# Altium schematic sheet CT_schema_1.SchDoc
size 623 x 258 mm
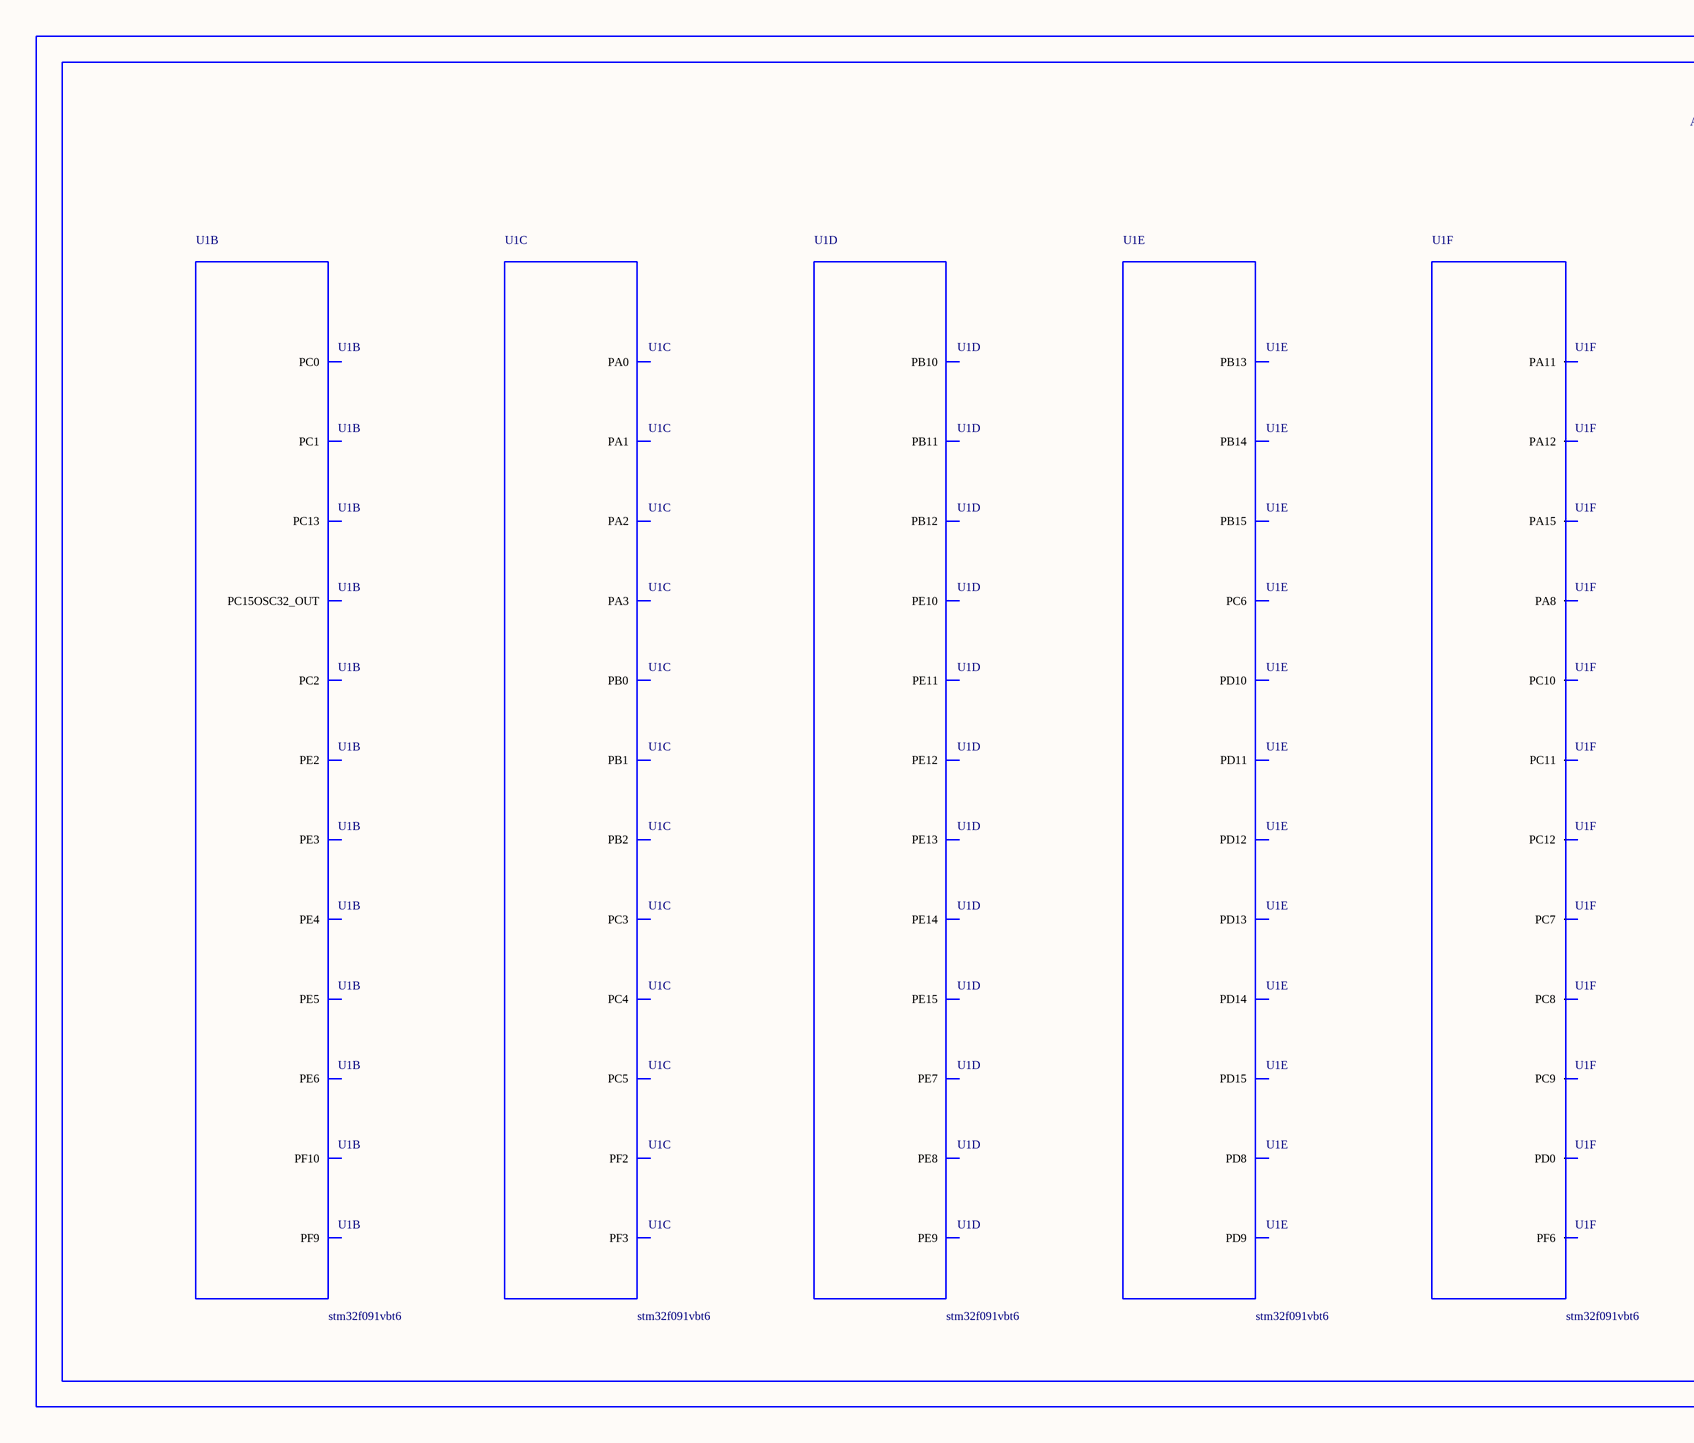
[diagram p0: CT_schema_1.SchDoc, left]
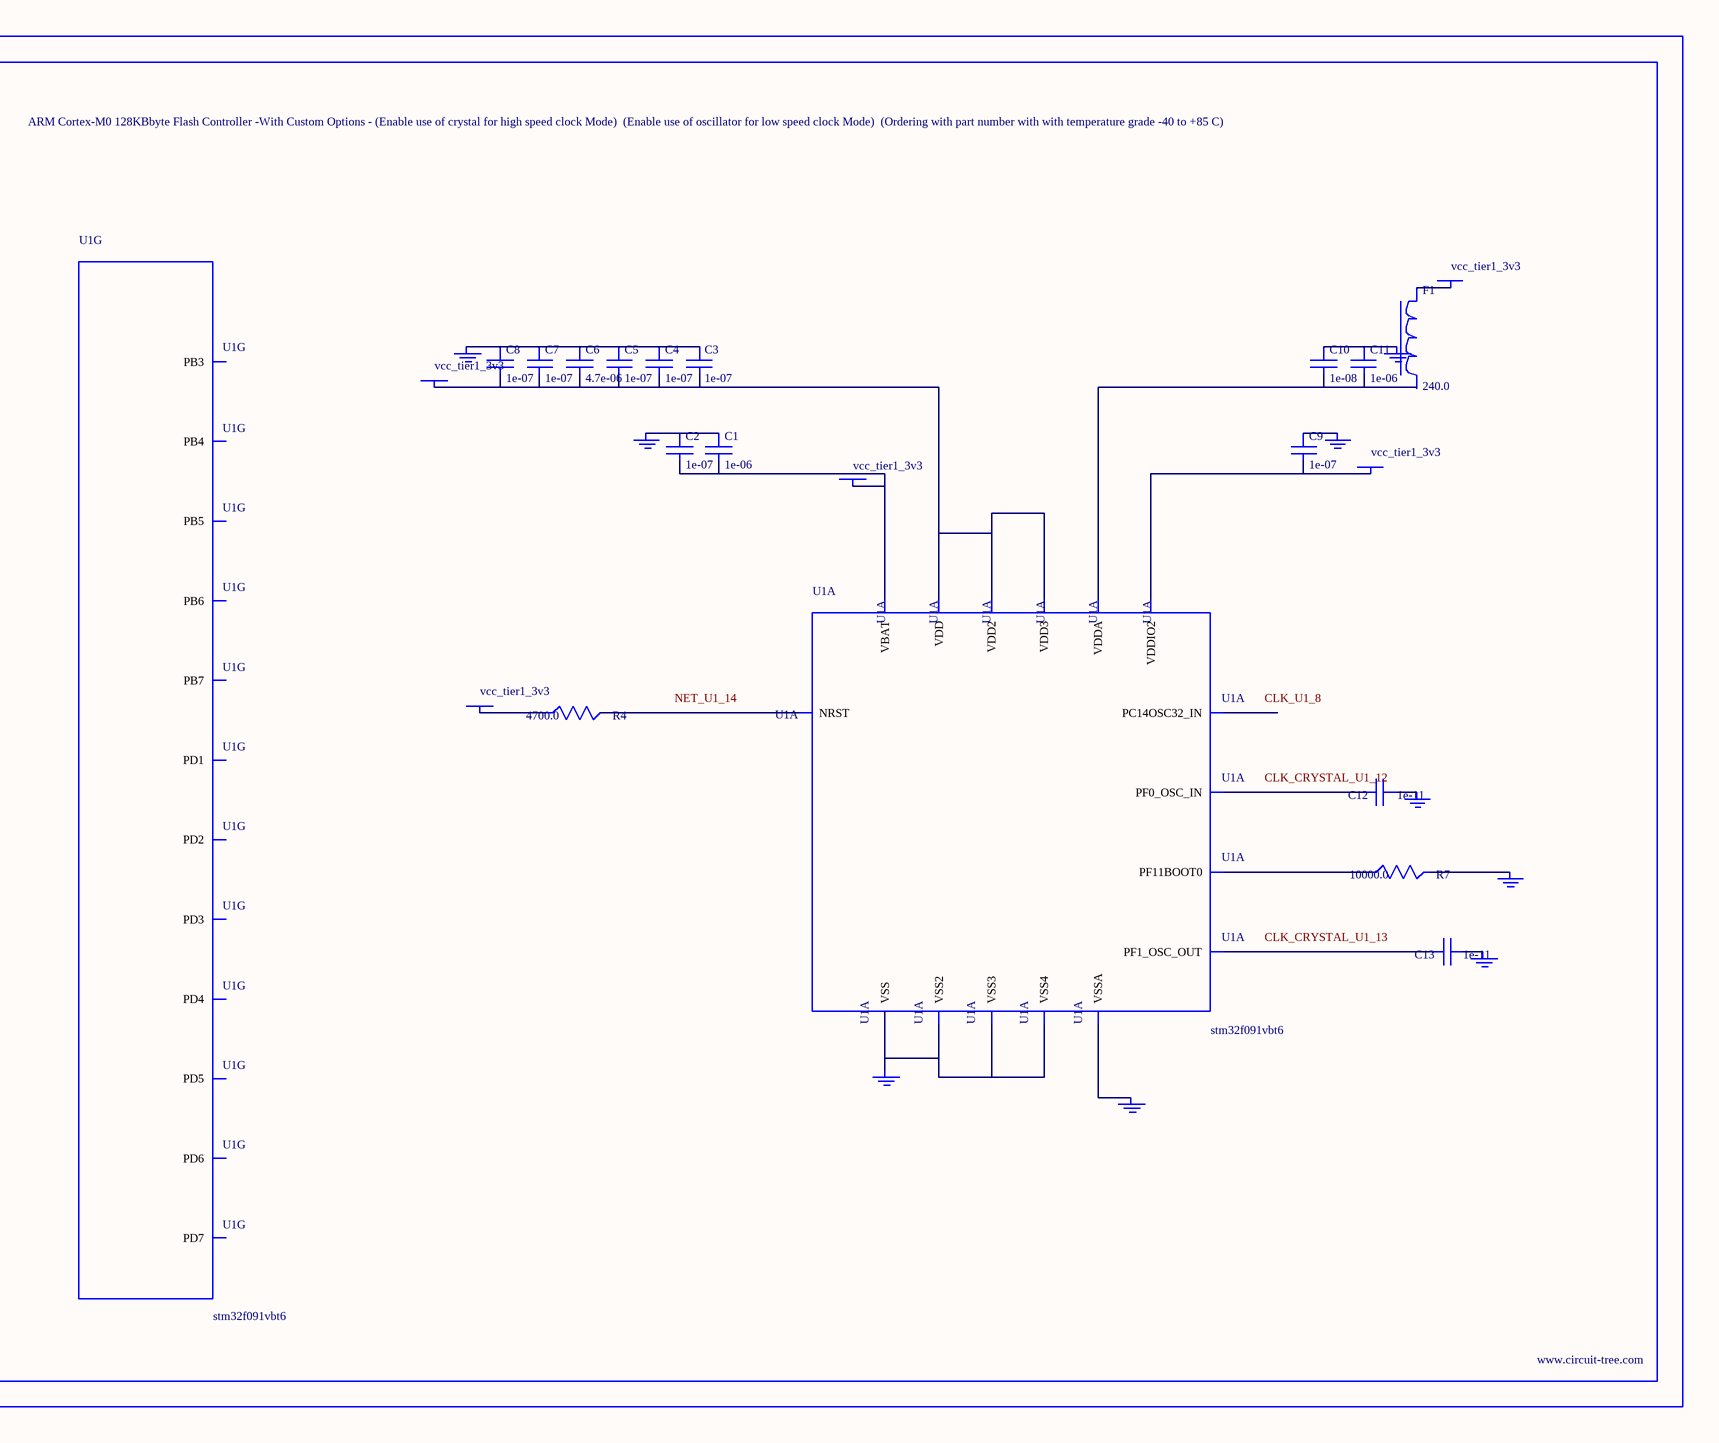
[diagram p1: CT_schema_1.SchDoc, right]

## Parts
BORDER0  (no value)
C1  1e-06  [C0603]
C2  1e-07  [C0603]
C3  1e-07  [C0603]
C4  1e-07  [C0603]
C5  1e-07  [C0603]
C6  4.7e-06  [C0603]
C7  1e-07  [C0603]
C8  1e-07  [C0603]
C9  1e-07  [C0603]
C10  1e-08  [C0603]
C11  1e-06  [C0603]
C12  1e-11  [C0402]
C13  1e-11  [C0402]
F1  240.0  [L0603]
GND_INSTANCE_0_0  (no value)
GND_INSTANCE_0_1  (no value)
GND_INSTANCE_0_2  (no value)
GND_INSTANCE_0_3  (no value)
GND_INSTANCE_0_4  (no value)
GND_INSTANCE_0_5  (no value)
GND_INSTANCE_0_6  (no value)
GND_INSTANCE_0_7  (no value)
GND_INSTANCE_0_8  (no value)
POWER_INSTANCE_0_0  vcc_tier1_3v3
POWER_INSTANCE_0_1  vcc_tier1_3v3
POWER_INSTANCE_0_2  vcc_tier1_3v3
POWER_INSTANCE_0_3  vcc_tier1_3v3
POWER_INSTANCE_0_4  vcc_tier1_3v3
R4  4700.0  [R0603]
R7  10000.0  [R0603]
U1  stm32f091vbt6  [LQFP100]  (parts A,B,C,D,E,F,G of 10)

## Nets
NetC1_1: C1.1 C2.1 GND_INSTANCE_0_0.0(GND)
NetC1_2: C1.2 C2.2 POWER_INSTANCE_0_0.0(PWR) U1.6(VBAT)
NetC3_1: C3.1 C4.1 C5.1 C6.1 C7.1 C8.1 GND_INSTANCE_0_5.0(GND)
NetC3_2: C3.2 C4.2 C5.2 C6.2 C7.2 C8.2 POWER_INSTANCE_0_2.0(PWR) U1.28(VDD) U1.50(VDD2) U1.100(VDD3)
NetC9_1: C9.1 GND_INSTANCE_0_6.0(GND)
NetC9_2: C9.2 POWER_INSTANCE_0_3.0(PWR) U1.75(VDDIO2)
NetC10_1: C10.1 C11.1 GND_INSTANCE_0_4.0(GND)
NetC10_2: C10.2 C11.2 U1.21(VDDA)
NetC12_1: C12.1 GND_INSTANCE_0_1.0(GND)
NetC12_2: C12.2 U1.12(PF0_OSC_IN)
NetC13_1: C13.1 GND_INSTANCE_0_2.0(GND)
NetC13_2: C13.2 U1.13(PF1_OSC_OUT)
NetF1_1: F1.1 POWER_INSTANCE_0_1.0(PWR)
NetGND_INSTANCE_0_3_0: GND_INSTANCE_0_3.0(GND) U1.20(VSSA)
NetGND_INSTANCE_0_7_0: GND_INSTANCE_0_7.0(GND) R7.2
NetGND_INSTANCE_0_8_0: GND_INSTANCE_0_8.0(GND) U1.27(VSS) U1.49(VSS2) U1.74(VSS3) U1.99(VSS4)
NetPOWER_INSTANCE_0_4_0: POWER_INSTANCE_0_4.0(PWR) R4.1
NetR4_2: R4.2 U1.14(NRST)
NetR7_1: R7.1 U1.94(PF11BOOT0)

Not connected (* = marked no-connect by the designer): F1 2; U1 1(PE2) 2(PE3) 3(PE4) 4(PE5) 5(PE6) 7(PC13) 8(PC14OSC32_IN) 9(PC15OSC32_OUT) 10(PF9) 11(PF10) 15(PC0) 16(PC1) 17(PC2) 18(PC3) 19(PF2) 22(PF3) 23(PA0) 24(PA1) 25(PA2) 26(PA3) 33(PC4) 34(PC5) 35(PB0) 36(PB1) 37(PB2) 38(PE7) 39(PE8) 40(PE9) 41(PE10) 42(PE11) 43(PE12) 44(PE13) 45(PE14) 46(PE15) 47(PB10) 48(PB11) 51(PB12) 52(PB13) 53(PB14) 54(PB15) 55(PD8) 56(PD9) 57(PD10) 58(PD11) 59(PD12) 60(PD13) 61(PD14) 62(PD15) 63(PC6) 64(PC7) 65(PC8) 66(PC9) 67(PA8) 70(PA11) 71(PA12) 73(PF6) 77(PA15) 78(PC10) 79(PC11) 80(PC12) 81(PD0) 82(PD1) 83(PD2) 84(PD3) 85(PD4) 86(PD5) 87(PD6) 88(PD7) 89(PB3) 90(PB4) 91(PB5) 92(PB6) 93(PB7)

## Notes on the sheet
- Labels drawn without touching a wire or pin: CLK_CRYSTAL_U1_12, CLK_CRYSTAL_U1_13, CLK_U1_8, NET_U1_14

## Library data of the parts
BORDER0 = BORDER_PAGE0
C1 C11 = C0603C105K3RACTU
C2-C5 C7-C9 = 06035C104K4Z2A
C6 = GRM188R6YA475KE15D
C10 = 06035C103K4Z2A
C12 C13 = C0402C100K3GACTU
F1 = Z0603C241ASMST
GND_INSTANCE_0_0-GND_INSTANCE_0_8 = GND
POWER_INSTANCE_0_0-POWER_INSTANCE_0_4 = PWR
R4 = RC0603JR-074K7L
R7 = RC0603JR-0710KL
